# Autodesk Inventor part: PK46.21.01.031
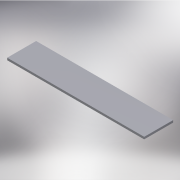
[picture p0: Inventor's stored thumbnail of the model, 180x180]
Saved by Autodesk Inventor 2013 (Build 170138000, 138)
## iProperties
Created: 2005-04
Part Number: PK46.21.01.031
Material: Steel, Mild
Document SubType Name: Modeling
Designer: salex
Manufacturer: Standard
Standards Organization: Custom
Density: 7.86 g/cm^3
Author: salex
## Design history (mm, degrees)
sketch "Эскиз1"
  geometry: L1 (0, 0)-(615, 0); L2 (615, 0)-(615, 130); L3 (615, 130)-(0, 130); L4 (0, 130)-(0, 0)
  constraints: 8 end point, 2 parallel, 1 horizontal, 1 perpendicular, 1 other
  dimensions: "d0" = 130 distance of L3.end L1.start; "d1" = 615 distance of L1.start L1.end
extrude "Выдавливание1" new body sketch "Эскиз1" distance "d2" = 10; taper "d3" = 0 deg
body "Solid1"
